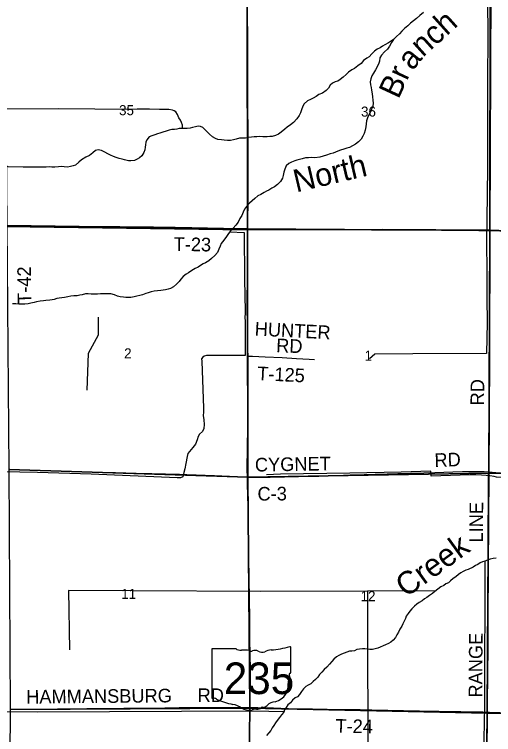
# Model space of a CAD drawing. Extents: x 1443599 to 1910620, y 1028088 to 1361369.
# Drawn here: x 1609762 to 1620320, y 1177322 to 1193177 of the extents above; entities that cross this region are included whole.
import ezdxf

# ---------------------------------------------------------------- set-up
doc = ezdxf.new("R2010")
doc.units = 0
for name, color, linetype in [('GM_X_County_Road', 7, 'Continuous'), ('GM_X_County_Road_Text', 7, 'Continuous'), ('GM_X_Major_River', 7, 'Continuous'), ('GM_X_Major_River_Text', 7, 'Continuous'), ('GM_X_Minor_River', 7, 'Continuous'), ('GM_X_Minor_River_Text', 7, 'Continuous'), ('GM_X_Section', 7, 'Continuous'), ('GM_X_Section_Text', 7, 'Continuous'), ('GM_X_State_Location', 7, 'Continuous'), ('GM_X_State_Route', 7, 'Continuous'), ('GM_X_State_Shield', 7, 'Continuous'), ('GM_X_Township', 7, 'Continuous'), ('GM_X_Township_Road', 7, 'Continuous'), ('GM_X_Township_Road_Text', 7, 'Continuous')]:
    doc.layers.add(name, color=color, linetype=linetype)

msp = doc.modelspace()

# ---------------------------------------------------------------- linework, layer by layer
at = {"layer": 'GM_X_County_Road'}
for points in [[(1614896, 1182992), (1614942, 1182992), (1615024, 1182991), (1615401, 1182993), (1615713, 1182996), (1616025, 1183002), (1616468, 1183015), (1616862, 1183029), (1617157, 1183040), (1617468, 1183051), (1617714, 1183056), (1617977, 1183063), (1618207, 1183069), (1618781, 1183085), (1619027, 1183095), (1619420, 1183107), (1619634, 1183112), (1619831, 1183116), (1619978, 1183116), (1620109, 1183113), (1620207, 1183106), (1620212, 1183106)], [(1620212, 1183106), (1620371, 1183091), (1620469, 1183084), (1620600, 1183078), (1620912, 1183074), (1621093, 1183072), (1621470, 1183070), (1622307, 1183062), (1622553, 1183060), (1623028, 1183053)]]:
    msp.add_lwpolyline(points, dxfattribs=at)
at = {"layer": 'GM_X_Major_River'}
for points in [[(1618773, 1193219), (1618696, 1193156), (1618621, 1193087), (1618556, 1193032), (1618489, 1192983), (1618428, 1192926), (1618359, 1192863), (1618296, 1192808), (1618249, 1192751), (1618184, 1192688), (1618114, 1192623), (1618071, 1192557), (1618026, 1192480), (1617979, 1192414), (1617916, 1192351), (1617854, 1192282), (1617817, 1192219), (1617806, 1192147), (1617785, 1192083), (1617715, 1191956), (1617672, 1191887), (1617641, 1191821), (1617617, 1191755), (1617604, 1191691), (1617607, 1191629), (1617624, 1191565), (1617631, 1191509), (1617646, 1191432), (1617653, 1191364), (1617658, 1191292), (1617665, 1191223), (1617658, 1191159), (1617628, 1191092), (1617601, 1191020), (1617566, 1190955), (1617539, 1190903), (1617518, 1190833), (1617509, 1190767), (1617508, 1190699), (1617493, 1190625), (1617471, 1190555), (1617440, 1190494), (1617401, 1190430), (1617342, 1190369)], [(1617342, 1190369), (1617275, 1190320), (1617211, 1190283), (1617144, 1190246), (1617086, 1190231), (1617017, 1190210), (1616949, 1190187), (1616888, 1190164), (1616836, 1190143), (1616785, 1190124), (1616719, 1190105), (1616636, 1190080), (1616562, 1190054), (1616492, 1190033), (1616383, 1190022), (1616313, 1190026), (1616241, 1190019), (1616179, 1190016), (1616106, 1189994), (1616042, 1189984), (1615988, 1189969), (1615938, 1189956), (1615871, 1189925), (1615812, 1189897), (1615749, 1189843), (1615722, 1189773), (1615697, 1189707), (1615684, 1189633), (1615667, 1189569), (1615624, 1189502), (1615558, 1189431), (1615490, 1189382), (1615437, 1189353), (1615366, 1189310), (1615316, 1189287), (1615263, 1189258), (1615192, 1189215), (1615128, 1189180), (1615059, 1189123), (1615004, 1189075), (1614939, 1189018), (1614876, 1188947), (1614830, 1188886), (1614803, 1188822), (1614770, 1188751), (1614731, 1188683), (1614690, 1188604), (1614642, 1188536), (1614585, 1188471), (1614532, 1188420), (1614481, 1188357), (1614434, 1188289), (1614375, 1188210), (1614321, 1188131), (1614298, 1188075), (1614265, 1188008), (1614238, 1187936), (1614181, 1187867), (1614108, 1187804), (1614043, 1187751), (1613974, 1187708), (1613923, 1187683), (1613863, 1187648), (1613812, 1187615), (1613742, 1187586), (1613669, 1187541), (1613598, 1187490), (1613545, 1187455), (1613480, 1187406), (1613431, 1187350), (1613390, 1187297), (1613337, 1187236), (1613268, 1187177), (1613204, 1187142), (1613149, 1187127), (1613091, 1187112), (1613037, 1187108), (1612987, 1187101), (1612916, 1187092), (1612844, 1187086), (1612778, 1187067), (1612709, 1187048), (1612655, 1187031), (1612583, 1187004), (1612526, 1186987), (1612462, 1186974), (1612398, 1186963), (1612325, 1186948), (1612271, 1186943), (1612219, 1186946), (1612163, 1186951), (1612091, 1186962), (1612037, 1186975), (1611966, 1187004), (1611890, 1187023), (1611812, 1187029), (1611762, 1187029), (1611712, 1187028), (1611658, 1187025), (1611594, 1187016), (1611523, 1187015)], [(1611523, 1187015), (1611455, 1187021), (1611391, 1187026), (1611327, 1187023), (1611259, 1187004), (1611207, 1186995), (1611144, 1186984), (1611072, 1186979), (1611008, 1186974), (1610938, 1186961), (1610864, 1186948), (1610807, 1186941), (1610749, 1186932), (1610699, 1186921), (1610639, 1186904), (1610592, 1186897), (1610543, 1186887), (1610456, 1186879), (1610403, 1186873), (1610331, 1186863), (1610253, 1186848), (1610199, 1186833), (1610128, 1186818), (1610064, 1186805), (1609994, 1186797), (1609860, 1186799), (1609792, 1186804), (1609724, 1186805)]]:
    msp.add_lwpolyline(points, dxfattribs=at)
at = {"layer": 'GM_X_Minor_River'}
for points in [[(1620187, 1194059), (1620186, 1193520), (1620196, 1192680), (1620186, 1191741), (1620183, 1190438), (1620186, 1189807), (1620177, 1189226), (1620173, 1188661), (1620165, 1188157), (1620172, 1187525), (1620171, 1186930), (1620178, 1186393)], [(1618114, 1192623), (1618001, 1192552), (1617926, 1192509), (1617874, 1192478), (1617821, 1192443), (1617756, 1192410), (1617694, 1192371), (1617639, 1192310), (1617577, 1192245), (1617525, 1192210), (1617456, 1192159), (1617403, 1192099), (1617330, 1192042), (1617255, 1191984), (1617198, 1191954), (1617125, 1191904), (1617074, 1191856), (1617005, 1191793), (1616940, 1191746), (1616888, 1191707), (1616831, 1191690), (1616771, 1191661), (1616720, 1191622), (1616685, 1191554), (1616628, 1191499), (1616547, 1191446), (1616472, 1191411), (1616408, 1191368), (1616347, 1191335), (1616286, 1191306), (1616222, 1191277), (1616149, 1191210), (1616116, 1191159), (1616086, 1191079), (1616065, 1191011), (1616036, 1190948), (1615987, 1190877), (1615915, 1190798), (1615847, 1190749), (1615774, 1190694), (1615723, 1190650), (1615642, 1190582), (1615581, 1190543), (1615518, 1190510), (1615444, 1190491), (1615392, 1190488), (1615334, 1190485), (1615235, 1190484), (1615159, 1190488), (1615105, 1190484), (1615043, 1190481), (1614983, 1190474), (1614921, 1190467), (1614857, 1190456), (1614786, 1190450), (1614724, 1190449), (1614650, 1190434), (1614588, 1190415), (1614523, 1190402), (1614455, 1190403), (1614385, 1190406), (1614327, 1190415), (1614247, 1190426), (1614194, 1190447), (1614128, 1190481), (1614063, 1190542), (1613990, 1190615), (1613915, 1190686), (1613862, 1190709), (1613808, 1190716), (1613749, 1190705), (1613685, 1190688), (1613633, 1190671), (1613568, 1190666), (1613506, 1190665), (1613450, 1190664), (1613396, 1190663), (1613344, 1190652), (1613288, 1190643), (1613228, 1190640), (1613169, 1190629), (1613107, 1190608), (1613034, 1190583), (1612968, 1190564), (1612912, 1190547), (1612859, 1190526), (1612787, 1190505), (1612734, 1190484), (1612679, 1190416), (1612660, 1190361), (1612649, 1190309), (1612643, 1190255), (1612636, 1190197), (1612612, 1190135), (1612567, 1190066), (1612516, 1190020), (1612464, 1189991), (1612407, 1189964), (1612331, 1189953), (1612275, 1189956), (1612191, 1189974)], [(1613450, 1190664), (1613469, 1190698), (1613466, 1190742), (1613446, 1190794), (1613423, 1190847), (1613388, 1190900), (1613357, 1190972), (1613320, 1191029), (1613283, 1191056), (1613243, 1191072), (1613167, 1191082), (1612963, 1191085), (1612740, 1191089), (1612468, 1191089), (1612150, 1191080), (1611537, 1191091), (1610742, 1191096), (1609514, 1191090)], [(1612191, 1189974), (1612138, 1189991), (1612072, 1190006), (1612004, 1190025), (1611944, 1190048), (1611877, 1190075), (1611823, 1190104), (1611756, 1190143), (1611682, 1190183), (1611608, 1190198), (1611552, 1190183), (1611491, 1190132), (1611418, 1190071), (1611333, 1190032), (1611240, 1189974), (1611179, 1189922), (1611110, 1189856), (1611058, 1189840), (1610999, 1189827), (1610931, 1189816), (1610859, 1189820), (1610791, 1189829), (1610731, 1189822), (1610655, 1189817), (1610589, 1189814), (1610525, 1189819), (1610464, 1189812), (1610398, 1189815)], [(1610398, 1189815), (1609954, 1189817), (1609624, 1189820), (1609572, 1189851), (1609514, 1189876), (1608569, 1189872), (1607427, 1189863), (1606298, 1189852), (1605122, 1189850), (1604289, 1189846)], [(1614507, 1188389), (1614822, 1188377), (1614829, 1187345), (1614845, 1186636), (1614842, 1186467)], [(1614845, 1186463), (1614845, 1185665), (1614043, 1185668), (1613995, 1185671), (1613944, 1185651), (1613912, 1185629), (1613888, 1185593), (1613892, 1185543), (1613926, 1184510), (1613926, 1184424), (1613925, 1184346), (1613933, 1184252), (1613942, 1184146), (1613933, 1184063), (1613905, 1183993), (1613844, 1183938), (1613814, 1183886), (1613789, 1183808), (1613751, 1183718), (1613692, 1183640), (1613587, 1183513), (1613572, 1183444), (1613539, 1183290), (1613514, 1183174), (1613498, 1183092), (1613477, 1183000), (1613425, 1182976), (1613347, 1182977), (1611451, 1183056), (1610272, 1183094), (1609490, 1183104)], [(1611608, 1186515), (1611611, 1186116), (1611388, 1185713), (1611362, 1184905)], [(1620178, 1186393), (1620163, 1185713), (1618540, 1185702), (1617705, 1185696), (1617586, 1185596)], [(1624367, 1182944), (1621562, 1182979), (1620387, 1182991), (1620331, 1183004), (1620237, 1183018), (1620155, 1183023), (1620051, 1183032), (1619930, 1183040), (1619794, 1183039), (1618945, 1183015), (1618934, 1183121), (1618281, 1183098), (1617152, 1183077), (1615622, 1183052), (1615317, 1183038)], [(1620374, 1181207), (1620310, 1181198), (1620244, 1181186), (1620184, 1181159), (1620127, 1181143), (1620075, 1181125), (1620023, 1181101), (1619973, 1181070), (1619920, 1181042), (1619868, 1181010), (1619760, 1180957), (1619707, 1180939), (1619649, 1180910), (1619597, 1180886), (1619547, 1180844), (1619488, 1180796), (1619428, 1180761), (1619374, 1180711), (1619323, 1180665), (1619271, 1180638)], [(1620127, 1181143), (1620119, 1177956), (1620099, 1176855), (1620093, 1174568), (1620075, 1172303), (1620065, 1170059), (1620066, 1168247), (1620057, 1165894), (1620065, 1164598)], [(1619271, 1180638), (1619221, 1180604), (1619160, 1180574), (1619090, 1180524), (1619029, 1180473), (1618973, 1180425), (1618909, 1180385), (1618852, 1180344), (1618798, 1180310), (1618748, 1180264), (1618681, 1180231), (1618631, 1180197), (1618575, 1180149), (1618516, 1180093), (1618478, 1180042), (1618441, 1179990), (1618397, 1179932), (1618377, 1179880), (1618348, 1179820), (1618324, 1179764), (1618295, 1179706), (1618255, 1179646), (1618222, 1179580), (1618188, 1179518), (1618161, 1179460), (1618109, 1179403), (1618053, 1179355), (1618002, 1179329), (1617940, 1179299), (1617884, 1179274), (1617824, 1179250), (1617773, 1179224), (1617713, 1179207), (1617653, 1179195), (1617593, 1179198), (1617539, 1179202), (1617483, 1179208), (1617429, 1179211), (1617369, 1179203), (1617307, 1179194), (1617256, 1179170), (1617196, 1179162), (1617142, 1179159), (1617086, 1179135), (1617026, 1179117), (1616970, 1179096), (1616911, 1179066), (1616857, 1179036), (1616803, 1178984), (1616756, 1178929), (1616704, 1178873), (1616647, 1178807), (1616587, 1178753), (1616538, 1178698), (1616488, 1178642), (1616445, 1178584), (1616395, 1178538), (1616343, 1178492), (1616290, 1178443), (1616236, 1178407), (1616184, 1178379), (1616131, 1178332), (1616087, 1178270), (1616042, 1178206), (1615998, 1178154), (1615948, 1178130), (1615893, 1178079), (1615849, 1178019), (1615790, 1177975), (1615750, 1177921), (1615716, 1177869), (1615697, 1177817), (1615645, 1177756), (1615602, 1177698), (1615550, 1177636), (1615515, 1177578), (1615477, 1177520), (1615439, 1177468), (1615410, 1177414), (1615368, 1177359), (1615317, 1177303)], [(1619046, 1180487), (1617542, 1180481), (1615175, 1180475), (1612380, 1180486), (1610957, 1180496), (1610974, 1179187)], [(1617542, 1180481), (1617548, 1176169), (1617537, 1172062), (1617517, 1167365)], [(1615699, 1177823), (1615039, 1177840), (1610265, 1177817), (1606864, 1177852), (1604515, 1177875)]]:
    msp.add_lwpolyline(points, dxfattribs=at)
at = {"layer": 'GM_X_Section'}
for points in [[(1614889, 1193763), (1614900, 1188455), (1609606, 1188532), (1609562, 1193798)], [(1614889, 1193763), (1620261, 1193747), (1620239, 1188421), (1614900, 1188455)], [(1620261, 1193747), (1625576, 1193507), (1625533, 1188242), (1620239, 1188421)], [(1609606, 1188532), (1614900, 1188455), (1614903, 1182988), (1609646, 1183160)], [(1614900, 1188455), (1620239, 1188421), (1620214, 1183081), (1614903, 1182988)], [(1620239, 1188421), (1625533, 1188242), (1625697, 1188238), (1625680, 1182986), (1620214, 1183081)], [(1609646, 1183160), (1614903, 1182988), (1614951, 1177902), (1609676, 1177878)], [(1614903, 1182988), (1620214, 1183081), (1620177, 1177794), (1614951, 1177902)], [(1625680, 1182986), (1625515, 1177701), (1620177, 1177794), (1620214, 1183081)], [(1609676, 1177878), (1614951, 1177902), (1614885, 1172491), (1609642, 1172633)], [(1614951, 1177902), (1620177, 1177794), (1620132, 1172489), (1614885, 1172491)], [(1620177, 1177794), (1625515, 1177701), (1625516, 1172427), (1620134, 1172459), (1620132, 1172489)]]:
    msp.add_lwpolyline(points, close=True, dxfattribs=at)
at = {"layer": 'GM_X_State_Route'}
for points in [[(1614894, 1183177), (1614902, 1184091), (1614902, 1184419), (1614902, 1184682), (1614900, 1185321), (1614900, 1185486), (1614899, 1185655), (1614898, 1185847), (1614898, 1186208), (1614897, 1186322), (1614893, 1186765), (1614896, 1187455), (1614897, 1187783), (1614898, 1188029), (1614901, 1188422), (1614902, 1188457), (1614905, 1188744), (1614910, 1188957), (1614911, 1189450), (1614910, 1190533), (1614910, 1190763), (1614909, 1190976), (1614907, 1191846), (1614904, 1192223), (1614902, 1192519), (1614897, 1193307)], [(1614898, 1182908), (1614896, 1182992), (1614894, 1183156), (1614894, 1183177)], [(1614947, 1177216), (1614953, 1177479), (1614957, 1177922), (1614957, 1177955), (1614960, 1178217), (1614963, 1178463), (1614961, 1178759), (1614952, 1179415), (1614946, 1179907), (1614940, 1180285), (1614933, 1180793), (1614923, 1181564), (1614916, 1182007), (1614910, 1182335), (1614899, 1182844), (1614898, 1182908)]]:
    msp.add_lwpolyline(points, dxfattribs=at)
at = {"layer": 'GM_X_State_Shield'}
for p, q in [((1614111, 1179196), (1614111, 1178140)), ((1614638, 1179214), (1614129, 1179214)), ((1615852, 1178688), (1615852, 1179241)), ((1615851, 1178688), (1615852, 1178688))]:
    msp.add_line(p, q, dxfattribs=at)
for centre, major_axis, start_param, end_param in [((1614131, 1179198), (20.2, 0), 1.712693, 3.28349), ((1614760, 1179337), (196, 0), 4.042523, 4.731795), ((1614824, 1178621), (702, 0), 1.404758, 1.657858), ((1614984, 1179204), (56.4, 0), 3.836095, 5.185415), ((1615067, 1179082), (117, 0), 0.950623, 2.079405), ((1615218, 1179249), (141, 0), 4.081561, 5.145723), ((1615467, 1178892), (371, 0), 1.699011, 2.107814), ((1615232, 1180655), (1845, 0), 4.814394, 5.042369), ((1615832, 1179243), (19.4, 0), 6.141152, 7.989035), ((1615847, 1178647), (30, 0), 1.883978, 3.671073), ((1615656, 1178577), (180, 0), 5.934695, 6.695948), ((1615831, 1178686), (20.7, 0), 5.05454, 6.418171), ((1615921, 1178457), (131, 0), 2.387724, 3.262537), ((1615335, 1178386), (462, 0), 5.101752, 6.440018), ((1614131, 1178137), (20.3, 0), 3.00124, 4.508301), ((1614135, 1178245), (155, 0), 4.665946, 4.897461), ((1614166, 1178079), (56, 0), 0.519207, 1.627899), ((1614873, 1179028), (1333, 0), 4.195997, 4.488961), ((1615530, 1177843), (253, 0), 1.647645, 2.488434), ((1614476, 1177665), (417, 0), 0.823519, 1.323587), ((1614927, 1178073), (265, 0), 4.026481, 4.996735), ((1615079, 1177708), (217, 0), 1.495662, 1.94098), ((1615099, 1177994), (141, 0), 4.691044, 5.507374), ((1615226, 1177892), (39.7, 0), 1.147584, 2.315152), ((1615209, 1178037), (149, 0), 4.937069, 5.64225)]:
    msp.add_ellipse(centre, major_axis=major_axis, ratio=0.8, start_param=start_param, end_param=end_param, dxfattribs=at)
at = {"layer": 'GM_X_Township'}
for points in [[(1636189, 1188034), (1630892, 1188083), (1625691, 1188229), (1625518, 1188234), (1622993, 1188324), (1620237, 1188424), (1620246, 1193716), (1620295, 1199077), (1620327, 1204365), (1620392, 1209603), (1620391, 1209712), (1620428, 1214993), (1620439, 1220361), (1625693, 1220296), (1625907, 1220301), (1631102, 1220200), (1636477, 1220086)], [(1620246, 1193716), (1620237, 1188424), (1617864, 1188439), (1614887, 1188433), (1609578, 1188508), (1604278, 1188533), (1599097, 1188589), (1598949, 1188592), (1593706, 1188658), (1588234, 1188703), (1588256, 1194003)], [(1588095, 1164852), (1588100, 1167517), (1588143, 1170151), (1588117, 1172813), (1588152, 1178106), (1588186, 1183430), (1588234, 1188703), (1593706, 1188658), (1598949, 1188592), (1599097, 1188589), (1604278, 1188533), (1609578, 1188508), (1614887, 1188433), (1617864, 1188439), (1620237, 1188424), (1620230, 1185626), (1620213, 1183050), (1620194, 1180346), (1620177, 1177790), (1620123, 1172454), (1620109, 1167154), (1620106, 1164621)], [(1635965, 1156490), (1631322, 1156526), (1630660, 1156530), (1630464, 1156532), (1625342, 1156563), (1625188, 1156564), (1622574, 1156580), (1620027, 1156604), (1620071, 1159262), (1620081, 1161924), (1620105, 1164447), (1620106, 1164621), (1620109, 1167154), (1620123, 1172454), (1620177, 1177790), (1620194, 1180346), (1620213, 1183050), (1620230, 1185626), (1620237, 1188424), (1622993, 1188324), (1625518, 1188234), (1625691, 1188229), (1630892, 1188083), (1636189, 1188034)]]:
    msp.add_lwpolyline(points, dxfattribs=at)
at = {"layer": 'GM_X_Township_Road'}
for points in [[(1620239, 1188419), (1620237, 1188642), (1620237, 1188823), (1620239, 1189364), (1620243, 1190021), (1620244, 1190530), (1620247, 1190940), (1620248, 1191071), (1620247, 1191267), (1620250, 1191480), (1620251, 1191661), (1620252, 1191956), (1620255, 1192399), (1620256, 1192793), (1620258, 1193236), (1620263, 1193729), (1620262, 1193745)], [(1609599, 1188516), (1609916, 1188513), (1610089, 1188512), (1610236, 1188511), (1610638, 1188509), (1610909, 1188508), (1611139, 1188507), (1611648, 1188507), (1611659, 1188507)], [(1611659, 1188507), (1611837, 1188507), (1612083, 1188505), (1612346, 1188503), (1612666, 1188499), (1612830, 1188497), (1612936, 1188496), (1613092, 1188494), (1613306, 1188492), (1613511, 1188489), (1613675, 1188485), (1613872, 1188480), (1614020, 1188477), (1614512, 1188465), (1614643, 1188462), (1614758, 1188460), (1614873, 1188458), (1614902, 1188457)], [(1614902, 1188457), (1614939, 1188456), (1615201, 1188453), (1615488, 1188451), (1615776, 1188449), (1616104, 1188448), (1616252, 1188447), (1616826, 1188443), (1617286, 1188439), (1617630, 1188438), (1617901, 1188437), (1618361, 1188438), (1618780, 1188436), (1618993, 1188435), (1619288, 1188431), (1619551, 1188431), (1619707, 1188428), (1619830, 1188426), (1619994, 1188423), (1620239, 1188419)], [(1620212, 1183106), (1620215, 1183193), (1620215, 1183407), (1620220, 1183932), (1620222, 1184391), (1620228, 1184769), (1620229, 1185261), (1620235, 1185754), (1620234, 1185983), (1620236, 1186197), (1620236, 1186410), (1620238, 1186706), (1620239, 1187116), (1620241, 1187756), (1620240, 1188265), (1620239, 1188396), (1620239, 1188419)], [(1620239, 1188419), (1620281, 1188418), (1620503, 1188411), (1620667, 1188406), (1621101, 1188386), (1621348, 1188379), (1621758, 1188364), (1622020, 1188353), (1622209, 1188348), (1622463, 1188338), (1622668, 1188333), (1623004, 1188322)], [(1614899, 1185655), (1614924, 1185654), (1615006, 1185651), (1615287, 1185640), (1615665, 1185622), (1615978, 1185605), (1616258, 1185588), (1616373, 1185579)], [(1609661, 1183164), (1609824, 1183155), (1610234, 1183142), (1610497, 1183136), (1610907, 1183124), (1611071, 1183117), (1611333, 1183109), (1611596, 1183101), (1611989, 1183090), (1612449, 1183079), (1612793, 1183069), (1613400, 1183056), (1613564, 1183051), (1614171, 1183028), (1614499, 1183015), (1614794, 1183000), (1614845, 1182997), (1614896, 1182992)], [(1620188, 1177818), (1620188, 1177843), (1620189, 1177909), (1620187, 1178138), (1620189, 1178302), (1620194, 1178762), (1620198, 1179139), (1620198, 1179336), (1620199, 1179812), (1620199, 1180305), (1620198, 1180797), (1620200, 1180978), (1620202, 1181158), (1620203, 1181355), (1620203, 1181667), (1620210, 1182652), (1620210, 1183046), (1620212, 1183106)], [(1609702, 1177881), (1609714, 1177881), (1610058, 1177885), (1611355, 1177896), (1612175, 1177904), (1613078, 1177913), (1613390, 1177916), (1613734, 1177918), (1614046, 1177921), (1614686, 1177922), (1614957, 1177922)], [(1614957, 1177922), (1615014, 1177922), (1615129, 1177919), (1615473, 1177909), (1615802, 1177899), (1616080, 1177892), (1616327, 1177889), (1616655, 1177885), (1617377, 1177872), (1617639, 1177867), (1618689, 1177848), (1619116, 1177840), (1620084, 1177821), (1620188, 1177818)], [(1620160, 1172502), (1620159, 1172532), (1620159, 1172611), (1620159, 1172841), (1620161, 1173038), (1620163, 1173153), (1620161, 1173300), (1620158, 1173547), (1620158, 1173908), (1620163, 1174252), (1620163, 1174400), (1620173, 1175467), (1620176, 1175992), (1620181, 1176271), (1620183, 1176481), (1620180, 1176842), (1620181, 1177219), (1620183, 1177482), (1620185, 1177728), (1620188, 1177818)], [(1620188, 1177818), (1620232, 1177817), (1620461, 1177810), (1620855, 1177802), (1621380, 1177789), (1621938, 1177777), (1622430, 1177765), (1622643, 1177762), (1622889, 1177755), (1623496, 1177740), (1624136, 1177728), (1624612, 1177724), (1624924, 1177721), (1625513, 1177717)]]:
    msp.add_lwpolyline(points, dxfattribs=at)

# ---------------------------------------------------------------- texts
at = {"layer": 'GM_X_County_Road_Text'}
for s, rotation, p in [('CYGNET', 1.0035, (1615064, 1183112)), ('RD', 1.9588, (1619022, 1183213)), ('C-3', 0.4591, (1615120, 1182473))]:
    msp.add_text(s, height=300, rotation=rotation, dxfattribs=at).set_placement(p)
at = {"layer": 'GM_X_Major_River_Text'}
for s, height, rotation, p in [('nch', 500.3, 42.0885, (1618760, 1192222)), ('a', 500, 51.0885, (1618534, 1191923)), ('Br', 500.3, 65.0877, (1618223, 1191296)), ('North', 500.3, 13.2, (1615972, 1189256))]:
    msp.add_text(s, height=height, rotation=rotation, dxfattribs=at).set_placement(p)
at = {"layer": 'GM_X_Minor_River_Text'}
msp.add_text('Creek', height=500.3, rotation=35.8451, dxfattribs=at).set_placement((1618390, 1180327))
at = {"layer": 'GM_X_Section_Text'}
for s, p in [('35', (1612068, 1190958)), ('36', (1617399, 1190927)), ('2', (1612180, 1185605)), ('1', (1617478, 1185555)), ('11', (1612116, 1180310)), ('12', (1617390, 1180259))]:
    msp.add_text(s, height=221, rotation=0, dxfattribs=at).set_placement(p)
at = {"layer": 'GM_X_State_Location'}
msp.add_text('235', height=1, rotation=0, dxfattribs=at).set_placement((1614609, 1178525))
for s in ['s', 'r']:
    msp.add_text(s, height=1, dxfattribs=at).set_placement((1614962, 1178598))
at = {"layer": 'GM_X_State_Shield'}
msp.add_text('235', height=696.1, dxfattribs=at).set_placement((1614375, 1178214))
at = {"layer": 'GM_X_Township_Road_Text'}
for s, rotation, p in [('T-23', 358.9384, (1613269, 1187973)), ('T-42', 90.7012, (1610136, 1186806)), ('HUNTER', 357.1207, (1615052, 1186108)), ('RD', 357.5316, (1615525, 1185743)), ('T-125', 357.1949, (1615107, 1185127)), ('RD', 89.5113, (1620110, 1184568)), ('LINE', 89.4278, (1620083, 1181550)), ('RANGE', 89.601, (1620070, 1178137)), ('HAMMANSBURG', 0.5148, (1610024, 1178004)), ('RD', 0, (1613799, 1178039)), ('T-24', 358.9397, (1616834, 1177365))]:
    msp.add_text(s, height=300, rotation=rotation, dxfattribs=at).set_placement(p)

doc.saveas('drawing.dxf')
